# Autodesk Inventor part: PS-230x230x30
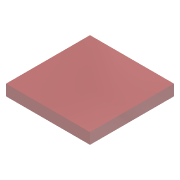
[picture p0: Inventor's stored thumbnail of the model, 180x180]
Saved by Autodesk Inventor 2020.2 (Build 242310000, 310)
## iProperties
Created: 2015-11
Part Number: PS-230x230x30
Material: Ogólny
Document SubType Name: Modeling
Designer: F.Stasiak
Density: 1 g/cm^3
Appearance: Ciemnoczerwone
Catalog Web Link: www.expertbooks.pl
Manager: www.cadconsulting.pl
Company: Fabian Stasiak CAD Consulting
Author: F.Stasiak
Subject: Zbiór ćwiczeń. Autodesk Inventor 2020. Kurs Professional
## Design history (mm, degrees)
sketch "Szkic1"
  geometry: L1 (-115, 115)-(115, 115); L2 (115, 115)-(115, -115); L3 (115, -115)-(-115, -115); L4 (-115, -115)-(-115, 115); L5 (-115, 115)-(115, -115); L6 (115, 115)-(-115, -115); 1 further point
  constraints: 12 end point, 2 midpoint, 2 parallel, 1 horizontal, 1 perpendicular
  dimensions: "d0" = 230 distance of L2.end L3.end; "d1" = 230 distance of L1.end L2.end
extrude "Wyciągnięcie proste1" new body sketch "Szkic1" distance "d2" = 30; taper "d3" = 0 deg
node "Bryła1"
